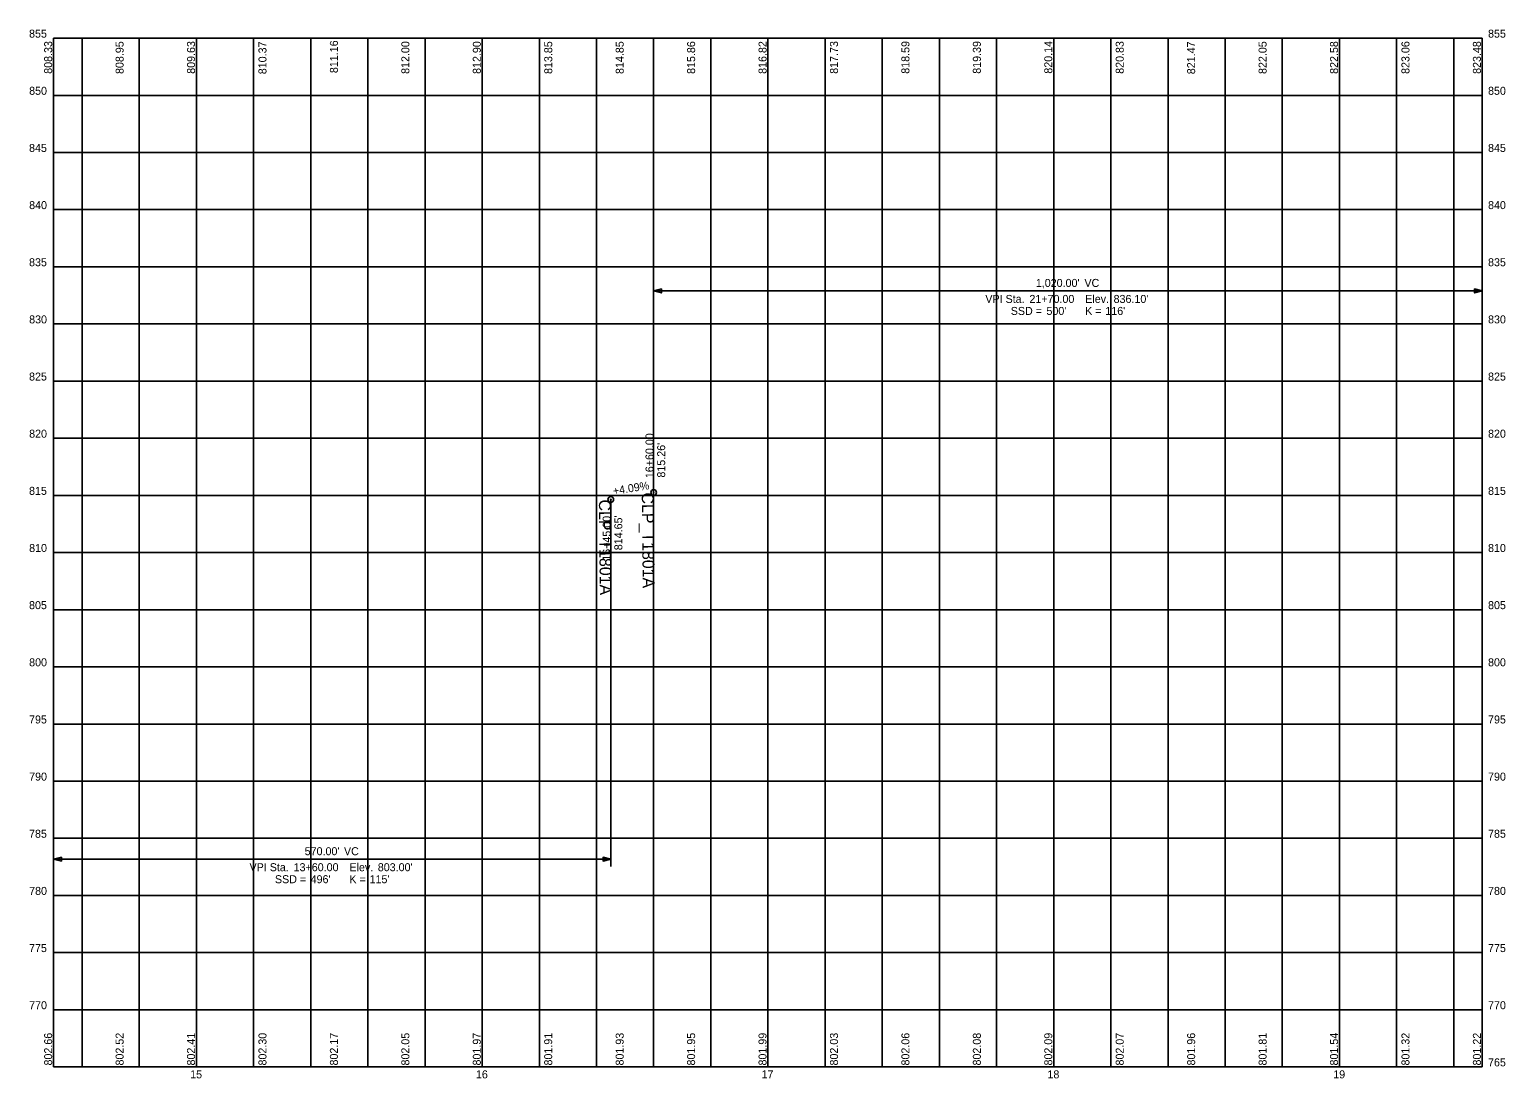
# Model space of a CAD drawing. Extents: x 672 to 1189, y 761 to 1128.
import ezdxf

# ---------------------------------------------------------------- set-up
doc = ezdxf.new("R2010")
doc.units = 0
for name, color, linetype in [('Default', 7, 'Continuous'), ('PF_P_Text', 7, 'Continuous'), ('PF_P_Text_Strip_Grades_20', 7, 'Continuous'), ('SH_Major_Grid_Line', 7, 'Continuous')]:
    doc.layers.add(name, color=color, linetype=linetype)

msp = doc.modelspace()

# ---------------------------------------------------------------- linework, layer by layer
at = {"layer": 'Default'}
for centre in [(890.78, 966.04), (875.78, 963.59)]:
    msp.add_circle(centre, 0.1, dxfattribs=at)
at = {"layer": 'PF_P_Text'}
for p, q in [((890.78, 1039.71), (890.78, 998.04)), ((890.78, 1036.66), (890.78, 1036.46)), ((890.78, 1036.56), (1180.78, 1036.56)), ((1180.78, 1036.46), (1180.78, 1036.66)), ((890.78, 998.04), (890.78, 1019.33)), ((890.78, 966.04), (890.78, 998.04)), ((875.78, 963.59), (875.78, 894.84)), ((875.78, 894.84), (875.78, 835.11)), ((680.78, 837.79), (680.78, 837.59)), ((680.78, 837.69), (875.78, 837.69)), ((875.78, 837.59), (875.78, 837.79))]:
    msp.add_line(p, q, dxfattribs=at)
for points in [[(890.78, 1036.56), (893.5, 1037.24), (893.5, 1035.88)], [(1180.78, 1036.56), (1178.06, 1035.88), (1178.06, 1037.24)], [(680.78, 837.69), (683.5, 838.37), (683.5, 837.01)], [(875.78, 837.69), (873.06, 837.01), (873.06, 838.37)]]:
    msp.add_lwpolyline(points, close=True, dxfattribs=at)
for centre in [(890.78, 966.04), (875.78, 963.59)]:
    msp.add_circle(centre, 1, dxfattribs=at)
at = {"layer": 'SH_Major_Grid_Line'}
for p, q in [((680.78, 1125), (1180.78, 1125)), ((680.78, 765), (680.78, 1125)), ((690.78, 765), (690.78, 1125)), ((710.78, 765), (710.78, 1125)), ((730.78, 765), (730.78, 1125)), ((750.78, 765), (750.78, 1125)), ((770.78, 765), (770.78, 1125)), ((790.78, 765), (790.78, 1125)), ((810.78, 765), (810.78, 1125)), ((830.78, 765), (830.78, 1125)), ((850.78, 765), (850.78, 1125)), ((870.78, 765), (870.78, 1125)), ((890.78, 765), (890.78, 1125)), ((910.78, 765), (910.78, 1125)), ((930.78, 765), (930.78, 1125)), ((950.78, 765), (950.78, 1125)), ((970.78, 765), (970.78, 1125)), ((990.78, 765), (990.78, 1125)), ((1010.78, 765), (1010.78, 1125)), ((1030.78, 765), (1030.78, 1125)), ((1050.78, 765), (1050.78, 1125)), ((1070.78, 765), (1070.78, 1125)), ((1090.78, 765), (1090.78, 1125)), ((1110.78, 765), (1110.78, 1125)), ((1130.78, 765), (1130.78, 1125)), ((1150.78, 765), (1150.78, 1125)), ((1170.78, 765), (1170.78, 1125)), ((1180.78, 765), (1180.78, 1125)), ((680.78, 1105), (1180.78, 1105)), ((680.78, 1085), (1180.78, 1085)), ((680.78, 1065), (1180.78, 1065)), ((680.78, 1045), (1180.78, 1045)), ((680.78, 1025), (1180.78, 1025)), ((680.78, 1005), (1180.78, 1005)), ((680.78, 985), (1180.78, 985)), ((680.78, 965), (1180.78, 965)), ((680.78, 945), (1180.78, 945)), ((680.78, 925), (1180.78, 925)), ((680.78, 905), (1180.78, 905)), ((680.78, 885), (1180.78, 885)), ((680.78, 865), (1180.78, 865)), ((680.78, 845), (1180.78, 845)), ((680.78, 825), (1180.78, 825)), ((680.78, 805), (1180.78, 805)), ((680.78, 785), (1180.78, 785)), ((680.78, 765), (1180.78, 765))]:
    msp.add_line(p, q, dxfattribs=at)

# ---------------------------------------------------------------- texts
at = {"layer": 'Default'}
for s, height, rotation, p in [('+4.09%', 2.8, 9.2833, (876.75, 965.14)), ('CLP_T1801A', 4.167, 270.5853, (871.61, 963.54)), ('CLP_T1801A', 4.167, 270.5853, (886.61, 965.99))]:
    msp.add_text(s, height=height, rotation=rotation, dxfattribs=at).set_placement(p)
at = {"layer": 'PF_P_Text'}
for s, p in [('855', (672.19, 1125.2)), ('855', (1182.78, 1125.2)), ('850', (672.22, 1105.2)), ('850', (1182.78, 1105.2)), ('845', (672.19, 1085.2)), ('845', (1182.78, 1085.2)), ('840', (672.22, 1065.2)), ('840', (1182.78, 1065.2)), ('835', (672.19, 1045.2)), ('835', (1182.78, 1045.2)), ("1,020.00'", (1024.52, 1037.96)), (' VC', (1040.49, 1037.96)), ('VPI Sta. ', (1006.85, 1032.36)), ('21+70.00', (1022.28, 1032.36)), ('   Elev. ', (1038.7, 1032.36)), ("836.10'", (1051.74, 1032.36)), ('830', (672.22, 1025.2)), ('SSD = ', (1015.74, 1028.16)), ("500'", (1028.24, 1028.16)), ('K = ', (1041.78, 1028.16)), ("116'", (1048.85, 1028.16)), ('830', (1182.78, 1025.2)), ('825', (672.19, 1005.2)), ('825', (1182.78, 1005.2)), ('820', (672.22, 985.2)), ('820', (1182.78, 985.2)), ('815', (672.19, 965.2)), ('815', (1182.78, 965.2)), ('810', (672.22, 945.2)), ('810', (1182.78, 945.2)), ('805', (672.19, 925.2)), ('805', (1182.78, 925.2)), ('800', (672.22, 905.2)), ('800', (1182.78, 905.2)), ('795', (672.19, 885.2)), ('795', (1182.78, 885.2)), ('790', (672.22, 865.2)), ('790', (1182.78, 865.2)), ('785', (672.19, 845.2)), ('785', (1182.78, 845.2)), ("570.00'", (768.65, 839.09)), (' VC', (781.36, 839.09)), ('VPI Sta. ', (749.35, 833.49)), ('SSD = ', (758.24, 829.29)), ('13+60.00', (764.78, 833.49)), ("496'", (770.74, 829.29)), ('K = ', (784.28, 829.29)), ('   Elev. ', (781.2, 833.49)), ("115'", (791.35, 829.29)), ("803.00'", (794.24, 833.49)), ('780', (672.22, 825.2)), ('780', (1182.78, 825.2)), ('775', (672.19, 805.2)), ('775', (1182.78, 805.2)), ('770', (672.22, 785.2)), ('770', (1182.78, 785.2)), ('765', (1182.78, 765.2)), ('15', (728.57, 761)), ('16', (828.58, 761)), ('17', (928.53, 761)), ('18', (1028.59, 761)), ('19', (1128.61, 761))]:
    msp.add_text(s, height=2.8, dxfattribs=at).set_placement(p)
for s, p in [('16+60.00', (890.73, 971.04)), ("815.26'", (894.81, 971.24)), ('16+45.00', (875.73, 942.13)), ("814.65'", (879.81, 945.82)), ('802.66', (680.28, 765.5)), ('802.52', (705.28, 765.5)), ('802.41', (730.28, 765.5)), ('802.30', (755.28, 765.5)), ('802.17', (780.28, 765.5)), ('802.05', (805.28, 765.5)), ('801.97', (830.28, 765.5)), ('801.91', (855.28, 765.5)), ('801.93', (880.28, 765.5)), ('801.95', (905.28, 765.5)), ('801.99', (930.28, 765.5)), ('802.03', (955.28, 765.5)), ('802.06', (980.28, 765.5)), ('802.08', (1005.28, 765.5)), ('802.09', (1030.28, 765.5)), ('802.07', (1055.28, 765.5)), ('801.96', (1080.28, 765.5)), ('801.81', (1105.28, 765.5)), ('801.54', (1130.28, 765.5)), ('801.32', (1155.28, 765.5)), ('801.22', (1180.28, 765.5))]:
    msp.add_text(s, height=2.8, rotation=90, dxfattribs=at).set_placement(p)
at = {"layer": 'PF_P_Text_Strip_Grades_20'}
for s, p in [('808.33', (680.28, 1112.54)), ('808.95', (705.28, 1112.48)), ('809.63', (730.28, 1112.54)), ('810.37', (755.28, 1112.39)), ('811.16', (780.28, 1112.79)), ('812.00', (805.28, 1112.5)), ('812.90', (830.29, 1112.5)), ('813.85', (855.29, 1112.48)), ('814.85', (880.29, 1112.48)), ('815.86', (905.29, 1112.5)), ('816.82', (930.29, 1112.52)), ('817.73', (955.28, 1112.54)), ('818.59', (980.28, 1112.56)), ('819.39', (1005.28, 1112.56)), ('820.14', (1030.28, 1112.59)), ('820.83', (1055.28, 1112.54)), ('821.47', (1080.28, 1112.39)), ('822.05', (1105.28, 1112.48)), ('822.58', (1130.28, 1112.51)), ('823.06', (1155.28, 1112.5)), ('823.48', (1180.28, 1112.51))]:
    msp.add_text(s, height=2.8, rotation=90, dxfattribs=at).set_placement(p)

doc.saveas('drawing.dxf')
